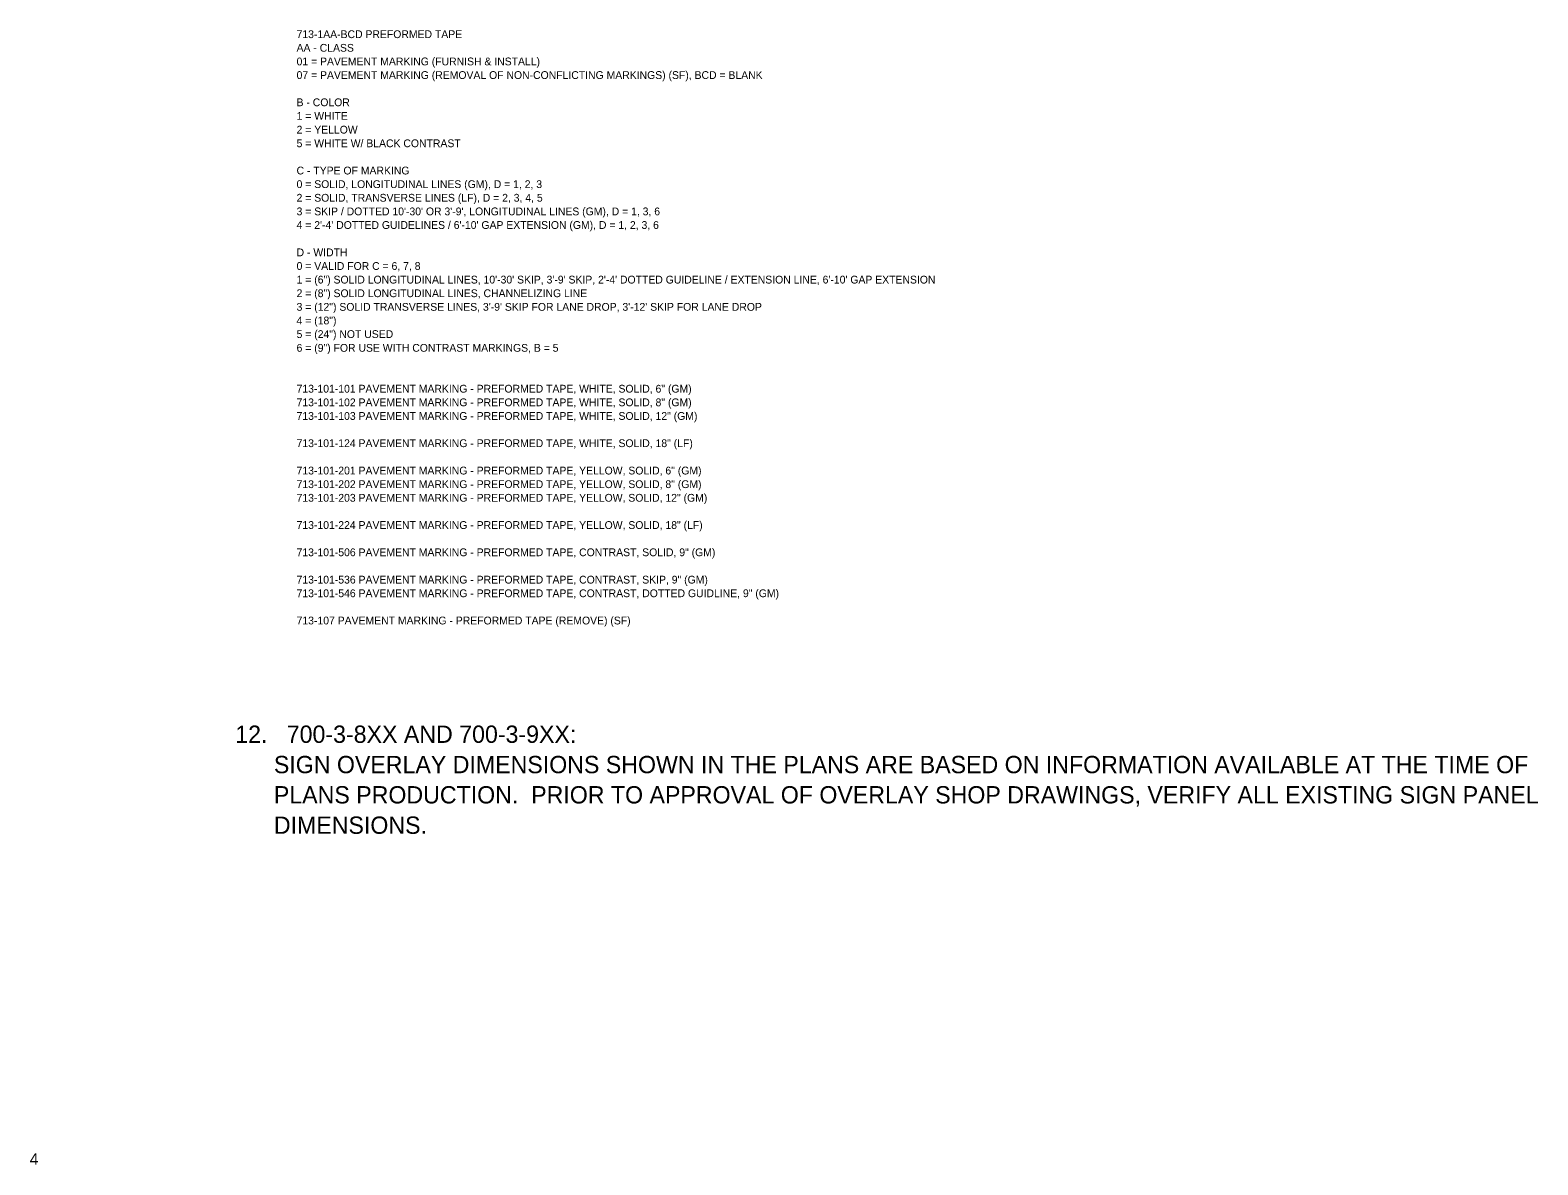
# Model space of a CAD drawing. Extents: x 2479959 to 2482822, y 3677554 to 3678604.
# Drawn here: x 2481516 to 2482822, y 3677579 to 3678562 of the extents above; entities that cross this region are included whole.
import ezdxf

# ---------------------------------------------------------------- set-up
doc = ezdxf.new("R2010")
doc.units = 0
for name, color, linetype in [('TextLabel', 7, 'Continuous'), ('TextNotes', 7, 'Continuous'), ('TextShtNo', 7, 'Continuous')]:
    doc.layers.add(name, color=color, linetype=linetype)

msp = doc.modelspace()

# ---------------------------------------------------------------- texts
at = {"layer": 'TextLabel'}
for s, p in [('713-1AA-BCD PREFORMED TAPE', (2481746.4, 3678555.4)), ('AA - CLASS', (2481746.4, 3678543.6)), ('01 = PAVEMENT MARKING (FURNISH & INSTALL)', (2481746.4, 3678531.8)), ('07 = PAVEMENT MARKING (REMOVAL OF NON-CONFLICTING MARKINGS) (SF), BCD = BLANK', (2481746.4, 3678520)), ('B - COLOR', (2481746.4, 3678496.4)), ('1 = WHITE', (2481746.4, 3678484.6)), ('2 = YELLOW', (2481746.4, 3678472.7)), ('5 = WHITE W/ BLACK CONTRAST', (2481746.4, 3678460.9)), ('0 = SOLID, LONGITUDINAL LINES (GM), D = 1, 2, 3', (2481746.4, 3678425.5)), ('C - TYPE OF MARKING', (2481746.4, 3678437.3)), ('2 = SOLID, TRANSVERSE LINES (LF), D = 2, 3, 4, 5', (2481746.4, 3678413.7)), ("3 = SKIP / DOTTED 10'-30' OR 3'-9', LONGITUDINAL LINES (GM), D = 1, 3, 6", (2481746.4, 3678401.9)), ("4 = 2'-4' DOTTED GUIDELINES / 6'-10' GAP EXTENSION (GM), D = 1, 2, 3, 6", (2481746.4, 3678390.1)), ('D - WIDTH', (2481746.4, 3678366.4)), ('0 = VALID FOR C = 6, 7, 8', (2481746.4, 3678354.6)), ('1 = (6") SOLID LONGITUDINAL LINES, 10\'-30\' SKIP, 3\'-9\' SKIP, 2\'-4\' DOTTED GUIDELINE / EXTENSION LINE, 6\'-10\' GAP EXTENSION', (2481746.4, 3678342.8)), ('2 = (8") SOLID LONGITUDINAL LINES, CHANNELIZING LINE', (2481746.4, 3678331)), ('4 = (18")', (2481746.4, 3678307.4)), ('3 = (12") SOLID TRANSVERSE LINES, 3\'-9\' SKIP FOR LANE DROP, 3\'-12\' SKIP FOR LANE DROP', (2481746.4, 3678319.2)), ('5 = (24") NOT USED', (2481746.4, 3678295.6)), ('6 = (9") FOR USE WITH CONTRAST MARKINGS, B = 5', (2481746.4, 3678283.7)), ('713-101-101 PAVEMENT MARKING - PREFORMED TAPE, WHITE, SOLID, 6" (GM)', (2481746.4, 3678248.3)), ('713-101-102 PAVEMENT MARKING - PREFORMED TAPE, WHITE, SOLID, 8" (GM)', (2481746.4, 3678236.5)), ('713-101-103 PAVEMENT MARKING - PREFORMED TAPE, WHITE, SOLID, 12" (GM)', (2481746.4, 3678224.7)), ('713-101-124 PAVEMENT MARKING - PREFORMED TAPE, WHITE, SOLID, 18" (LF)', (2481746.4, 3678201.1)), ('713-101-201 PAVEMENT MARKING - PREFORMED TAPE, YELLOW, SOLID, 6" (GM)', (2481746.4, 3678177.4)), ('713-101-202 PAVEMENT MARKING - PREFORMED TAPE, YELLOW, SOLID, 8" (GM)', (2481746.4, 3678165.6)), ('713-101-203 PAVEMENT MARKING - PREFORMED TAPE, YELLOW, SOLID, 12" (GM)', (2481746.4, 3678153.8)), ('713-101-224 PAVEMENT MARKING - PREFORMED TAPE, YELLOW, SOLID, 18" (LF)', (2481746.4, 3678130.2)), ('713-101-506 PAVEMENT MARKING - PREFORMED TAPE, CONTRAST, SOLID, 9" (GM)', (2481746.4, 3678106.6)), ('713-101-536 PAVEMENT MARKING - PREFORMED TAPE, CONTRAST, SKIP, 9" (GM)', (2481746.4, 3678082.9)), ('713-101-546 PAVEMENT MARKING - PREFORMED TAPE, CONTRAST, DOTTED GUIDLINE, 9" (GM)', (2481746.4, 3678071.1)), ('713-107 PAVEMENT MARKING - PREFORMED TAPE (REMOVE) (SF)', (2481746.4, 3678047.5))]:
    msp.add_text(s, height=6.75, dxfattribs=at).set_placement(p)
at = {"layer": 'TextNotes'}
for s, p in [('12.   700-3-8XX AND 700-3-9XX:', (2481693.3, 3677944.9)), ('      SIGN OVERLAY DIMENSIONS SHOWN IN THE PLANS ARE BASED ON INFORMATION AVAILABLE AT THE TIME OF', (2481693.3, 3677918.6)), ('      PLANS PRODUCTION.  PRIOR TO APPROVAL OF OVERLAY SHOP DRAWINGS, VERIFY ALL EXISTING SIGN PANEL', (2481693.3, 3677892.4)), ('      DIMENSIONS.', (2481693.3, 3677866.1))]:
    msp.add_text(s, height=15, dxfattribs=at).set_placement(p)
at = {"layer": 'TextShtNo'}
msp.add_text('4', height=10, rotation=360, dxfattribs=at).set_placement((2481515.3, 3677579.4))

doc.saveas('drawing.dxf')
